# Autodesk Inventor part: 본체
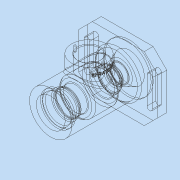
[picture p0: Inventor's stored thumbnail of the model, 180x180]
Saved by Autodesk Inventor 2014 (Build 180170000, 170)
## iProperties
Created: 2017-10
Part Number: 본체
Material: 알루미늄 6061
Document SubType Name: Modeling
Designer: kb542-18
Density: 2.71 g/cm^3
Appearance: 알루미늄 - 평지
Mass: 790.921 g
Surface Area: 663.849 cm^2
Volume: 291.853 cm^3
Author: kb542-18
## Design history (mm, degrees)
sketch "스케치1"
  geometry: C1 r 31 at (0, 0); 1 further point
  constraints: 1 centre point, 1 coincident
  dimensions: "d0" = 62 diameter of C1
extrude "돌출1" new body sketch "스케치1" stored distance "d1" = 99; taper "d2" = 0 deg
sketch "스케치2"
  geometry: L1 (-47, 58)-(47, 58); L2 (47, 58)-(47, -58); L3 (47, -58)-(-47, -58); L4 (-47, -58)-(-47, 58); L5 (-47, 58)-(47, -58); L6 (47, 58)-(-47, -58); C1 r 31 at (0, 0) reference
  constraints: 12 end point, 2 midpoint, 2 parallel, 1 horizontal, 1 perpendicular
  dimensions: "d3" = 116 distance of L3.end L1.start; "d4" = 94 distance of L2.end L3.end
extrude "돌출2" join sketch "스케치2" distance "d5" = 13; taper "d6" = 0 deg
sketch "스케치3"
  geometry: C1 r 35 at (0, 0); 1 further point
  constraints: 1 centre point, 1 coincident
  dimensions: "d7" = 70 diameter of C1
extrude "돌출3" join sketch "스케치3" distance "d8" = 3; taper "d9" = 0 deg
chamfer "모따기1" distance "d10" = 20; stored, may be unused: second distance "d11" = 2, angle "d12" = 45 deg
sketch "스케치4"
  geometry: L1 (-47, 38)-(-47, -38) reference; L2 (-20, -46)-(20, -46); L3 (-20, -42)-(20, -42); L4 (20, -50)-(-20, -50); C1 r 31 at (0, 0) reference; A1 r 4 centre (-20, -46) between (-20, -42) and (-20, -50); A2 r 4 centre (20, -46) between (20, -50) and (20, -42); 1 further point
  constraints: 8 end point, 4 point on circle, 4 tangent, 2 centre point, 1 midpoint, 1 parallel, 1 perpendicular, 1 vertical alignment
  dimensions: "d13" = 46 distance of C1.centre point (0, -46); "d14" = 4 radius of A2; "d15" = 40 distance of L2.end L2.start
extrude "돌출4" cut sketch "스케치4" stored distance "d16" = 3; taper "d17" = 0 deg
sketch "스케치5"
  geometry: L1 (-49.5, 31)-(-49.5, -31) reference; L2 (-49.5, 0)-(-40.5, 0); L3 (-40.5, 0)-(-40.5, 21); L4 (-40.5, 21)-(-49.5, 21); L5 (-49.5, 21)-(-49.5, 0); L6 (-40.5, 0)-(-37.5, 0); L7 (-37.5, 0)-(-37.5, 24); L8 (-37.5, 24)-(-40.5, 24); L9 (-40.5, 24)-(-40.5, 0); L10 (-37.5, 0)-(-28.5, 0); L11 (-28.5, 0)-(-28.5, 20); L12 (-28.5, 20)-(-37.5, 20); L13 (-37.5, 20)-(-37.5, 0); L14 (-28.5, 0)-(-25.25, 0); L15 (-25.25, 0)-(-25.25, 17.5); L16 (-25.25, 17.5)-(-28.5, 17.5); L17 (-28.5, 17.5)-(-28.5, 0); L18 (-25.25, 0)-(-23.5, 0); L19 (-23.5, 0)-(-23.5, 18.5); L20 (-23.5, 18.5)-(-25.25, 18.5); L21 (-25.25, 18.5)-(-25.25, 0); L22 (-23.5, 0)-(-12.5, 0); L23 (-12.5, 0)-(-12.5, 17.5); L24 (-12.5, 17.5)-(-23.5, 17.5); L25 (-23.5, 17.5)-(-23.5, 0); L26 (-12.5, 0)-(25.5, 0); L27 (25.5, 0)-(25.5, 26); L28 (25.5, 26)-(-12.5, 26); L29 (-12.5, 26)-(-12.5, 0); L30 (25.5, 0)-(36.5, 0); L31 (36.5, 0)-(36.5, 17.5); L32 (36.5, 17.5)-(25.5, 17.5); L33 (25.5, 17.5)-(25.5, 0); L34 (36.5, 0)-(41.5, 0); L35 (41.5, 0)-(41.5, 16); L36 (41.5, 16)-(36.5, 16); L37 (36.5, 16)-(36.5, 0); L38 (41.5, 0)-(41.5, 0); L39 (41.5, 0)-(41.5, 10); L40 (41.5, 12.858)-(41.5, 0); L41 (41.5, 0)-(44.2, 0); L42 (44.2, 0)-(44.2, 10); L43 (44.2, 10)-(41.5, 10); L44 (41.5, 10)-(41.5, 0); L45 (44.2, 0)-(51.5, 0); L46 (51.5, 0)-(51.5, 12.5); L47 (51.5, 12.5)-(44.2, 12.5); L48 (44.2, 12.5)-(44.2, 0); L49 (65.5, -35)-(65.5, 35) reference; L50 (65.5, 22)-(51.5, 16); L51 (51.5, 16)-(51.5, 0); L52 (51.5, 0)-(65.5, 0); L53 (65.5, 0)-(65.5, 22); 1 further point
  constraints: 102 end point, 23 parallel, 14 perpendicular, 12 horizontal, 3 collinear, 1 midpoint
  dimensions: "d18" = 3 distance of L7.end L8.end; "d20" = 21 distance between parallel lines of L17 L1; "d21" = 12 distance between parallel lines of L13 L1; "d23" = 14 distance between parallel lines of L49 L51; "d24" = 38 distance between parallel lines of L33 L29; "d25" = 11 distance of L23.end L24.end; "d26" = 1.75 distance of L19.end L20.end; "d27" = 11 distance of L31.end L32.end; "d32" = 7.3 distance of L46.end L47.end; "d33" = 2.7 distance of L39.end L42.end; "d34" = 42 diameter of L4 L2; "d35" = 48 diameter of L8 L6; "d36" = 40 diameter of L12 L10; "d37" = 35 diameter of L16 L14; "d38" = 37 diameter of L20 L18; "d39" = 35 diameter of L24 L22; "d40" = 52 diameter of L28 L26; "d41" = 35 diameter of L32 L30; "d42" = 32 diameter of L36 L34; "d43" = 20 diameter of L43 L41; "d44" = 25 diameter of L47 L45; "d47" = 22 distance of L52.end L50.start; "d48" = 32 diameter of L50.end L52; "d49" = 26 distance between parallel lines of L19 L1
revolve "회전1" sketch "스케치5" stored, may be unused: angle "d50" = 90 deg
node "작업 평면1"
sketch "스케치6"
  geometry: L1 (49.5, -31)-(49.5, 31) reference; C1 r 25 at (-6.5, 0); 1 further point
  constraints: 1 centre point, 1 horizontal alignment
  dimensions: "d52" = 50 diameter of C1; "d53" = 56 distance from line of L1 C1.centre
extrude "돌출5" join sketch "스케치6" stored distance "d54" = 3; taper "d55" = 0 deg
sketch "스케치7"
  geometry: C1 r 25 at (0, 0) reference; C2 r 16 at (0, 0); 1 further point
  constraints: 1 centre point, 1 coincident
  dimensions: "d56" = 32 diameter of C2
extrude "돌출6" cut sketch "스케치7" stored distance "d57" = 3; taper "d58" = 0 deg
fillet "모깎기1" dims "d59" = 0.3
chamfer "모따기2" distance "d60" = 0.7; stored, may be unused: second distance "d61" = 2, angle "d62" = 30 deg
fillet "모깎기2" dims "d63" = 3
chamfer "모따기3" distance "d64" = 1; stored, may be unused: second distance "d65" = 2, angle "d66" = 33 deg
node "작업 평면2"
sketch "스케치8"
  geometry: L1 (-31.5, -47)-(18.5, -47) reference; L2 (49.5, -31)-(49.5, 31) reference; 2 further points
  constraints: 1 other
  dimensions: "d67" = 10 distance from line of L1 point (-6.5, -37); "d69" = 56 distance from line of point (-6.5, -37) L2
feature "엠보싱1" sketch "스케치8" dims "d70" = 0.5, "d71" = 0
feature "스레드1" dims "d72" = 10, "d73" = 0
sketch "스케치9"
  geometry: L1 (0, 0)-(0, 20.5); L2 (0, 0)-(0, -20.5); C1 r 17 at (0, 0) reference; A1 r 20.5 centre (0, 0) between (0, 20.5) and (0, -20.5); 3 further points
  constraints: 4 end point, 3 coincident, 2 point on circle, 1 centre point, 1 collinear, 1 vertical
  dimensions: "d74" = 41 diameter of A1
hole "구멍1" sketch "스케치9" at (0, 20.5), (0, -20.5) diameter "d75" = 2.459; stored, may be unused: countersink angle "d79" = 90 deg, drill point angle "d81" = 118 deg; dims "d76" = 6, "d77" = 4, "d78" = 2, "d80" = 8
fillet "모깎기3" dims "d82" = 3
chamfer "모따기4" distance "d83" = 1; stored, may be unused: second distance "d84" = 2, angle "d85" = 45 deg
node "솔리드1"
mirror "대칭1"
other parameters: "d51" = -47
